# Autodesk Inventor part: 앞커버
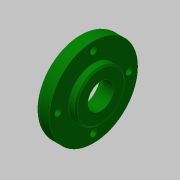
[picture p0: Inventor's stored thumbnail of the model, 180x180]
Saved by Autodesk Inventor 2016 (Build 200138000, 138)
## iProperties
Created: 2015-12
Part Number: 앞커버
Document SubType Name: Modeling
Designer: mdu
Density: 2.71 g/cm^3
Material: 알루미늄 6061
Appearance: 진녹색
Mass: 71.0233 g
Surface Area: 94.1949 cm^2
Volume: 26.2078 cm^3
Author: mdu
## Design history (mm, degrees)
sketch "스케치1"
  geometry: L1 (-7.5, 0)-(7.5, 0); L2 (-7.5, 0)-(-7.5, 31); L3 (-7.5, 31)-(2.5, 31); L4 (2.5, 31)-(2.5, 17.5); L5 (2.5, 17.5)-(7.5, 17.5); L6 (7.5, 17.5)-(7.5, 0); 2 further points
  constraints: 12 end point, 3 perpendicular, 1 coincident, 1 horizontal, 1 midpoint, 1 parallel
  dimensions: "d0" = 15 distance of L1.start L1.end; "d1" = 62 diameter of L3 L1; "d2" = 35 diameter of L5 L1; "d5" = 10 distance of L2.end L3.end
revolve "회전1" sketch "스케치1" stored, may be unused: angle "d6" = 90 deg
sketch "스케치2" dims "d42" = 50
  geometry: 3 further points
  constraints: 2 vertical alignment, 1 coincident, 2 other
hole "구멍1" sketch "스케치2" at (0, 25) diameter "d8" = 4.5; stored, may be unused: countersink angle "d12" = 90 deg, drill point angle "d14" = 118 deg; dims "d9" = 6, "d10" = 8, "d11" = 4.4, "d13" = 8
hole "구멍2" diameter "d20" = 18; stored, may be unused: countersink angle "d24" = 90 deg, drill point angle "d26" = 0 deg; dims "d18" = 10, "d19" = 10, "d21" = 6, "d22" = 8, "d23" = 4.4, "d25" = 8
hole "구멍3" diameter "d34" = 30; stored, may be unused: countersink angle "d38" = 90 deg, drill point angle "d40" = 0 deg; dims "d32" = 10, "d33" = 10, "d35" = 6, "d36" = 4, "d37" = 2, "d39" = 7.3
fillet "모깎기1" dims "d27" = 3, "d41" = 0.3
chamfer "모따기1" distance "d29" = 0.7; stored, may be unused: second distance "d30" = 2, angle "d31" = 30 deg
chamfer "모따기2" distance "d44" = 1; stored, may be unused: second distance "d45" = 2, angle "d46" = 45 deg
node "솔리드1"
pattern_circular "원형 패턴1" dims angle "d16" = 360 deg
